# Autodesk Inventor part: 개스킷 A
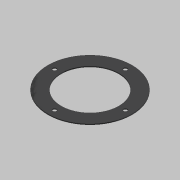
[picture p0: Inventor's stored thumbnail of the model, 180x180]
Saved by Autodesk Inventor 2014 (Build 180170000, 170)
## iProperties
Created: 2020-08
Part Number: 개스킷 A
Material: 고무
Document SubType Name: Modeling
Designer: mduedu
Density: 0.93 g/cm^3
Appearance: 고무 - 검은색 - 버전 1.1
Mass: 3.44685 g
Surface Area: 79.7179 cm^2
Volume: 3.70629 cm^3
Author: mduedu
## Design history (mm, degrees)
sketch "스케치1"
  geometry: C1 r 47.5 at (0, 0); C2 r 32.5 at (0, 0); 1 further point
  constraints: 2 centre point, 2 coincident
  dimensions: "d0" = 95 diameter of C1; "d1" = 65 diameter of C2
extrude "돌출1" new body sketch "스케치1" distance "d2" = 1; taper "d3" = 0 deg
sketch "스케치2" dims "d4" = 80
  geometry: 3 further points
  constraints: 2 vertical alignment, 1 coincident, 2 other
hole "구멍1" sketch "스케치2" at (0, 40) diameter "d5" = 4.5; stored, may be unused: countersink angle "d9" = 90 deg, drill point angle "d11" = 118 deg; dims "d6" = 6, "d7" = 4, "d8" = 2, "d10" = 8
node "솔리드1"
pattern_circular "원형 패턴1" dims angle "d13" = 360 deg
